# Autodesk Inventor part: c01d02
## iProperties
Created: 2004-05
Part Number: c01d02
Document SubType Name: Modeling
Designer: CADCIM Technologies
Manufacturer: Standard
Standards Organization: Custom
Author: CADCIM Technologies
